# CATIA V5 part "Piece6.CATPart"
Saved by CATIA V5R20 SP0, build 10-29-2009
Part number: Piece6
Bounding box of the stored display mesh (mm): x 0 to 100, y 0 to 580, z -135.197 to 0
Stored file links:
  C:\Users\Lambert\Desktop\IAO\Piece6.CATPart
  C:\Users\Lambert\Desktop\IAO\Produit1.CATProduct
  C:\Users\Lambert\Desktop\IAO\skl_general.CATPart
  C:\Users\Lambert\Desktop\IAO\Piece1.CATPart
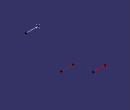
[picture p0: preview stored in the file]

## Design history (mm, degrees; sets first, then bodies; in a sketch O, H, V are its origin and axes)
Set1
  Plane1 "Plan_Ref": linked copy from another document
  Point1 "A": linked copy from another document
  DatumPoint1 "D": linked copy from another document
  Point2 "G": linked copy from another document
Set2
  Line1 "Axe_pivot_10": type Normal, RefPoint Point1, RefSkin Plane1, Start 0, End 100
  Line2 "Axe_pivot_50": type Normal, RefPoint DatumPoint1, RefSkin Plane1, Start 0, End 100
  Line3 "Axe_pivot_30": type Normal, RefPoint Point2, RefSkin Plane1, Start 0, End 100
Body1 (main body)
